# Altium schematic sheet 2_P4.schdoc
size 423 x 300 mm
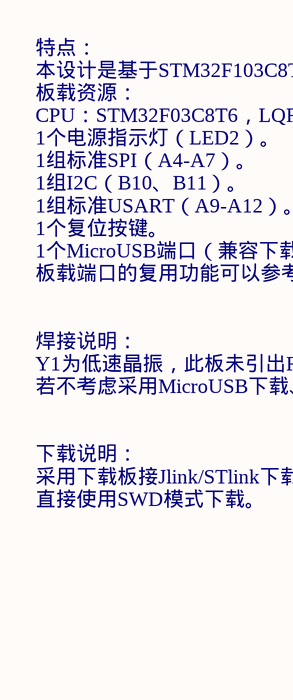
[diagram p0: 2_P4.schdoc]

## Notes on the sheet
- 特点：
  本设计是基于STM32F103C8T6芯片的Mini板其主要特点在于在保障基本功能的前提下，将板子大小缩减至2.5cm，只有一元硬币大小，十分适用于做较小的设计的开发。
  板载资源：
  CPU：STM32F03C8T6，LQFP48，Flash：128K，SRAM：20K。
  1个电源指示灯（LED2）。
  1组标准SPI（A4-A7）。
  1组I2C（B10、B11）。
  1组标准USART（A9-A12）。
  1个复位按键。
  1个MicroUSB端口（兼容下载与供电）。
  板载端口的复用功能可以参考数据手册。
- 焊接说明：
  Y1为低速晶振，此板未引出RTC电源接口，因此不需焊接，C7、C8为其外围电容也无需焊接。
  若不考虑采用MicroUSB下载、供电，也可不焊接，但下载口依然需要从MicroUSB焊盘引出。
- 下载说明：
  采用下载板接Jlink/STlink下载。
  直接使用SWD模式下载。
